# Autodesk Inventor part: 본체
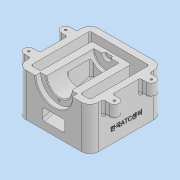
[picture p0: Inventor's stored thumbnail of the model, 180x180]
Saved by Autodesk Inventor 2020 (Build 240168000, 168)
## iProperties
Created: 2022-03
Part Number: 본체
Material: 일반
Document SubType Name: Modeling
Designer: Administrator
Density: 1 g/cm^3
Appearance: 기본값
Author: Administrator
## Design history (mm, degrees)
sketch "스케치1"
  geometry: L1 (55, -55)-(-55, -55); L2 (-55, -55)-(-55, 55); L3 (-55, 55)-(55, 55); L4 (55, 55)-(55, -55); L5 (55, -55)-(-55, 55); L6 (-55, -55)-(55, 55); 1 further point
  constraints: 12 end point, 2 midpoint, 2 parallel, 1 horizontal, 1 perpendicular
  dimensions: "d0" = 110 distance of L1.start L1.end; "d1" = 110 distance of L1.end L2.end
extrude "돌출1" new body sketch "스케치1" distance "d2" = 65; taper "d3" = 0 deg
fillet "모깎기1" dims "d4" = 13
sketch "스케치2"
  geometry: L1 (-55, 42)-(-55, -42) reference; L2 (-42, -55)-(42, -55) reference; L3 (55, -42)-(55, 42) reference; L4 (42, 55)-(-42, 55) reference; L5 (-45, 42)-(-45, -42); L6 (-42, -45)-(42, -45); L7 (45, -42)-(45, 42); L8 (42, 45)-(-42, 45); L9 (-30, 33)-(30, 33); L10 (30, 33)-(30, -45); L11 (30, -45)-(-30, -45); L12 (-30, -45)-(-30, 33); A1 r 13 centre (-42, 42) between (-42, 55) and (-55, 42) reference; A2 r 13 centre (-42, -42) between (-55, -42) and (-42, -55) reference; A3 r 13 centre (42, -42) between (42, -55) and (55, -42) reference; A4 r 13 centre (42, 42) between (55, 42) and (42, 55) reference; A5 r 3 centre (-42, 42) between (-42, 45) and (-45, 42); A6 r 3 centre (-42, -42) between (-45, -42) and (-42, -45); A7 r 3 centre (42, -42) between (42, -45) and (45, -42); A8 r 3 centre (42, 42) between (45, 42) and (42, 45); 3 further points
  constraints: 16 end point, 8 point on circle, 4 centre point, 2 parallel, 1 collinear, 1 horizontal, 1 perpendicular
  dimensions: "d5" = 25 distance between parallel lines of L12 L1; "d6" = 25 distance between parallel lines of L3 L10; "d7" = 88 distance between parallel lines of L9 L2
extrude "돌출2" cut sketch "스케치2" extent not by distance; stored distance "d8" = 0; taper "d9" = 0 deg
sketch "스케치3"
  geometry: L1 (0, 65)-(84, 65) reference; 2 further points
  constraints: 1 midpoint
hole "구멍1" sketch "스케치3" at (42, 65) diameter "d10" = 38; stored, may be unused: countersink angle "d14" = 90 deg, drill point angle "d16" = 0 deg; dims "d11" = 9, "d12" = 56, "d13" = 8, "d15" = 80
sketch "스케치4"
  geometry: L1 (-19, 0)-(19, 0) reference; L2 (-42, -65)-(42, -65) reference; C1 r 7.5 at (0, 0); A1 r 19 centre (0, 0) between (-19, 0) and (19, 0) reference; 3 further points
  constraints: 2 midpoint, 1 centre point, 1 coincident, 1 vertical alignment
  dimensions: "d17" = 15 diameter of C1
extrude "돌출3" cut sketch "스케치4" distance "d18" = 4; taper "d19" = -30 deg
sketch "스케치5"
  geometry: L1 (42, 55)-(-42, 55) reference; L2 (-65, 35)-(-55, 35); L3 (-65, 21)-(-55, 21); L4 (-55, 42)-(-55, -42) reference; A1 r 7 centre (-65, 28) between (-65, 35) and (-65, 21); 1 further point
  constraints: 4 end point, 2 horizontal, 2 point on circle, 2 point on line, 2 tangent, 1 centre point
  dimensions: "d20" = 65 horizontal distance of A1.centre point (0, 0); "d21" = 27 distance from line of L1 A1.centre; "d22" = 14 diameter of A1
extrude "돌출4" join sketch "스케치5" distance "d23" = 20; taper "d24" = 0 deg
sketch "스케치6"
  geometry: A1 r 7 centre (-65, 28) between (-65, 35) and (-65, 21) reference; 2 further points
  constraints: 1 coincident
hole "구멍2" sketch "스케치6" at (-65, 28) diameter "d25" = 3.242; stored, may be unused: countersink angle "d29" = 90 deg, drill point angle "d31" = 118 deg; dims "d26" = 9, "d27" = 56, "d28" = 8, "d30" = 11
fillet "모깎기2" dims "d32" = 3, "d33" = 1
chamfer "모따기1" distance "d34" = 1; stored, may be unused: second distance "d35" = 2, angle "d36" = 45 deg
sketch "스케치8"
  geometry: L1 (0, -33)-(65, -33) reference; L2 (30, -33)-(9.1, 45); L3 (9.1, 45)-(0, 45); L4 (65, 42)-(0, 42) reference; L5 (0, 42)-(0, -42) reference; L6 (65, 55)-(0, 55) reference; L7 (0, 42)-(0, 55) reference; L8 (46, -24)-(46, 46) reference; L9 (65, 42)-(65, -30) reference; 2 further points
  constraints: 4 end point, 2 point on line, 1 parallel
  dimensions: "d40" = 30 distance from line of L5 L2.start; "d41" = 75 deg angle of L1 L2; "d42" = 10 distance between parallel lines of L3 L6
extrude "돌출5" cut sketch "스케치8" stored distance "d46" = 60; taper "d47" = 0 deg
fillet "모깎기3" dims "d48" = 3
sketch "스케치9"
  geometry: A1 r 20 centre (0, 0) between (-20, 0) and (20, 0) reference; 2 further points
  constraints: 1 vertical alignment
  dimensions: "d49" = 23 distance of point (0, -23) A1.centre
hole "구멍3" sketch "스케치9" at (0, -23) diameter "d50" = 3.242; stored, may be unused: countersink angle "d54" = 90 deg, drill point angle "d56" = 118 deg; dims "d51" = 9, "d52" = 56, "d53" = 8, "d55" = 11
sketch "스케치11"
  geometry: L1 (11.164, 37.296)-(29.404, -30.776) reference; L2 (65, 55)-(0, 55) reference; L3 (32.302, -33)-(65, -33) reference; L4 (65, -42)-(65, 42) reference; L5 (11.597, 55)-(31.425, -19); L6 (29.197, 55)-(38.843, 19); L7 (65, 21)-(65, -21) reference; L8 (65, -19)-(31.425, -19); L9 (38.843, 19)-(65, 19); L10 (65, 19)-(65, -19); 3 further points
  constraints: 10 end point, 3 point on line, 1 horizontal, 1 parallel
  dimensions: "d58" = 36 distance between parallel lines of L9 L2; "d59" = 38 distance between parallel lines of L8 L9; "d60" = 17 distance between parallel lines of L5 L6; "d61" = 75 deg angle of L3 L5; "d62" = 11.59685 distance of L5.start L2.end
extrude "돌출6" cut sketch "스케치11" stored distance "d63" = 34; taper "d64" = 0 deg
fillet "모깎기4" dims "d65" = 3
fillet "모깎기5" dims "d66" = 3
fillet "모깎기6" dims "d67" = 3
fillet "모깎기7" dims "d68" = 3
sketch "스케치12"
  geometry: L1 (-13, 65)-(-13, 0) reference; L2 (0, 0)-(84, 0) reference; 3 further points
  constraints: 1 coincident, 1 other
  dimensions: "d69" = 55 distance from line of L1 point (42, 20); "d70" = 20 distance from line of L2 point (42, 20)
feature "엠보싱1" sketch "스케치12" dims "d0" = 110, "d1" = 110, "d71" = 0.5, "d72" = 0
node "솔리드1"
mirror "미러1"
mirror "미러2"
node "투영된 루프1"
node "투영된 루프2"
feature "A9D066F2-1C7D-4E18-AEED-F7BC21143FA4" dims "d10" = 38, "d11" = 9, "d12" = 56, "d13" = 8, "d14" = 90 deg, "d15" = 80, "d16" = 0
